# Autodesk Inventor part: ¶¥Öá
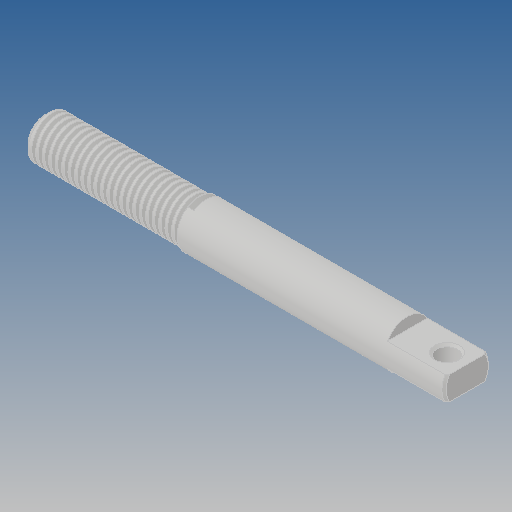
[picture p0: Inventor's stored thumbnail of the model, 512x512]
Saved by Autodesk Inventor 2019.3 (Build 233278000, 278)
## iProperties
Created: 2017-08
Part Number: ¶¥Öá
Material: Ogólny
Document SubType Name: Modeling
Designer: Admin
Density: 1 g/cm^3
Appearance: Domyślna
Author: Admin
Revision Number: ÈÎºÎ
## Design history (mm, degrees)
feature "ÊäÈë1"
node "Bryła1"
